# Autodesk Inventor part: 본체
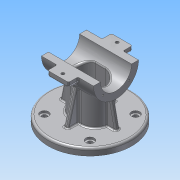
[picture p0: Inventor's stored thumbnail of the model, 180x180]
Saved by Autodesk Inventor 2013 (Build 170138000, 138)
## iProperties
Created: 2015-12
Part Number: 본체
Material: 알루미늄 6061
Document SubType Name: Modeling
Designer: mduedu
Density: 2.71 g/cm^3
Mass: 580.908 g
Surface Area: 555.601 cm^2
Volume: 214.357 cm^3
Author: mduedu
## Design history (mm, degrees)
sketch "스케치1"
  geometry: L1 (45, 40)-(-45, 40); L2 (-45, 40)-(-45, -40); L3 (-45, -40)-(45, -40); L4 (45, -40)-(45, 40); L5 (45, 40)-(-45, -40); L6 (-45, 40)-(45, -40); 2 further points
  constraints: 12 end point, 2 midpoint, 2 parallel, 1 coincident, 1 horizontal, 1 perpendicular, 3 other
  dimensions: "d0" = 90 distance of L2.end L3.end; "d2" = 80 distance of L1.end L2.end
extrude "돌출1" new body sketch "스케치1" distance "d3" = 10; taper "d4" = 0 deg
sketch "스케치2"
  geometry: C1 r 32.5 at (80, 0); 1 further point
  constraints: 1 centre point
  dimensions: "d5" = 65 diameter of C1; "d116" = 80 distance of point (0, 0) C1.centre
extrude "돌출2" join sketch "스케치2" stored distance "d7" = 75; taper "d8" = 0 deg
sketch "스케치3"
  geometry: L1 (-27.5, -20)-(27.5, -20); L2 (27.5, -20)-(27.5, 20); L3 (27.5, 20)-(-27.5, 20); L4 (-27.5, 20)-(-27.5, -20); L5 (-27.5, -20)-(27.5, 20); L6 (27.5, -20)-(-27.5, 20); 1 further point
  constraints: 12 end point, 2 midpoint, 2 parallel, 1 horizontal, 1 perpendicular
  dimensions: "d9" = 55 distance of L2.end L3.end; "d11" = 40 distance of L1.end L2.end
extrude "돌출3" new body sketch "스케치3" stored distance "d12" = 75; taper "d13" = 0 deg
fillet "모깎기1"
fillet "모깎기2"
feature "결합1"
  node "솔리드2"
sketch "스케치4"
  geometry: L1 (-37.5, 47.5)-(37.5, 47.5) reference; L2 (32.5, 47.5)-(40.208, 10); L3 (37.5, 47.5)-(37.5, 112.5) reference; L4 (60.208, 0)-(60.208, 10) reference; L5 (60.208, 10)-(-60.208, 10) reference; 1 further point
  constraints: 2 end point, 2 point on line
  dimensions: "d15" = 5 distance from line of L2.start L3; "d117" = 20 distance from line of L2.end L4
sketch "스케치5"
  geometry: L1 (10, 35.208)-(56.729, 22.687); L2 (0, 60.208)-(10, 60.208) reference; L3 (10, -60.208)-(10, 60.208) reference; 2 further points
  constraints: 2 end point, 1 point on line, 2 other
  dimensions: "d118" = 25 distance from line of L1.start L2; "d119" = 75 deg angle of L1 L3
feature "리브1" dims "d19" = 1, "d20" = 6, "d21" = 0, "d22" = 0, "d23" = 1, "d24" = 1
feature "리브2" dims "d25" = 1, "d26" = 6, "d27" = 0, "d28" = 0, "d29" = 1, "d30" = 1
fillet "모깎기4" dims "d31" = 2
fillet "모깎기5" dims "d32" = 2
fillet "모깎기6" dims "d33" = 2
sketch "스케치6"
  geometry: L1 (0, 0)-(-32.88, 32.88); L2 (0, 0)-(-46.5, 0); A1 r 46.5 centre (0, 0) between (-32.88, 32.88) and (-46.5, 0); 5 further points
  constraints: 4 end point, 2 coincident, 2 point on circle, 1 centre point, 1 horizontal, 5 other
  dimensions: "d120" = 93 diameter of A1; "d122" = 45 deg angle of L1 L2; "d126" = 360 deg dimension on point (0, 0) point (-32.88, 32.88) (derived)
hole "구멍1" sketch "스케치6" at (-32.88, 32.88), (-32.88, -32.88), (32.88, -32.88), (32.88, 32.88) diameter "d34" = 7; stored, may be unused: countersink angle "d38" = 90 deg, drill point angle "d40" = 118 deg; dims "d35" = 6, "d36" = 12, "d37" = 3, "d39" = 8
fillet "모깎기13" dims "d131" = 3
hole "구멍2" diameter "d44" = 45; stored, may be unused: countersink angle "d48" = 90 deg, drill point angle "d50" = 118 deg; dims "d42" = 10, "d43" = 10, "d45" = 6, "d46" = 4, "d47" = 2, "d49" = 8
sketch "스케치7" dims "d52" = 26.5
  geometry: L1 (0, 0)-(32.5, 0); L2 (0, 0)-(22.981, 22.981); A1 r 32.5 centre (0, 0) between (32.5, 0) and (22.981, 22.981) reference; 3 further points
  constraints: 4 end point, 2 point on circle, 1 coincident, 1 horizontal, 1 point on line, 3 other
  dimensions: "d51" = 45 deg angle of L2 L1
hole "구멍3" sketch "스케치7" at (18.738, 18.738) diameter "d54" = 2.459; stored, may be unused: countersink angle "d58" = 90 deg, drill point angle "d60" = 118 deg; dims "d55" = 8, "d56" = 4, "d57" = 2, "d59" = 10
sketch "스케치8"
  geometry: L1 (72.5, 31.623)-(72.5, 46); L2 (72.5, 46)-(87.5, 46); L3 (87.5, 46)-(87.5, 31.623); A1 r 32.5 centre (80, 0) between (87.5, 31.623) and (72.5, 31.623) reference; 2 further points
  constraints: 6 end point, 2 point on circle, 1 horizontal, 1 midpoint, 1 parallel, 1 vertical, 1 vertical alignment
  dimensions: "d64" = 15 distance of L1.end L2.end; "d66" = 46 distance from line of L2 A1.centre
extrude "돌출4" join sketch "스케치8" stored distance "d67" = 30; taper "d68" = 0 deg
fillet "모깎기8" dims "d69" = 3
fillet "모깎기9" dims "d70" = 2
node "작업 평면2"
sketch "스케치16"
  geometry: L1 (33.166, 72.5)-(44, 72.5) reference; L2 (42.5, 72.5)-(28.53, 64.434); L3 (46, 75.5)-(46, 84.5) reference; 2 further points
  constraints: 2 end point, 1 point on line, 2 other
  dimensions: "d138" = 30 deg angle of L2 L1; "d139" = 3.5 distance from line of L2.start L3
feature "리브3" sketch "스케치16" dims "d140" = 1, "d141" = 3, "d142" = 0, "d143" = 0, "d144" = 1, "d145" = 1
fillet "모깎기14" dims "d146" = 1
fillet "모깎기15" dims "d147" = 1
sketch "스케치9"
  geometry: L1 (-76, 82.5)-(76, 82.5); L2 (76, 82.5)-(76, 0); L3 (76, 0)-(-76, 0); L4 (-76, 0)-(-76, 82.5); L5 (-46, 4.5)-(-46, -4.5) reference; C1 r 32.5 at (0, 0) reference; 2 further points
  constraints: 8 end point, 2 parallel, 1 coincident, 1 horizontal, 1 midpoint, 1 perpendicular
  dimensions: "d71" = 50 distance edge to line of C1 L1; "d72" = 30 distance between parallel lines of L4 L5
extrude "돌출5" cut sketch "스케치9" stored distance "d73" = 0; taper "d74" = 0 deg
node "작업 평면1"
sketch "스케치10"
  geometry: L1 (-7.5, 15)-(7.5, 15); L2 (-7.5, -15)-(7.5, -15); A1 r 20 centre (-7.5, 0) between (-7.5, 20) and (-26.977, 4.545) reference; A2 r 20 centre (7.5, 0) between (26.977, 4.545) and (7.5, 20) reference; A3 r 15 centre (-7.5, 0) between (-7.5, 15) and (-7.5, -15); A4 r 15 centre (7.5, 0) between (7.5, -15) and (7.5, 15); 1 further point
  constraints: 7 point on circle, 4 end point, 4 tangent, 3 point on line, 2 centre point, 2 coincident, 1 horizontal
  dimensions: "d77" = 5 radial gap between concentric circles of A3 A1
extrude "돌출6" cut sketch "스케치10" stored distance "d78" = 50; taper "d79" = 0 deg
fillet "모깎기10" dims "d80" = 3
sketch "스케치11"
  geometry: 2 further points
  constraints: 1 coincident
hole "구멍4" sketch "스케치11" at (0, 0) diameter "d81" = 12; stored, may be unused: countersink angle "d85" = 90 deg, drill point angle "d87" = 118 deg; dims "d82" = 8, "d83" = 40, "d84" = 10, "d86" = 10
sketch "스케치12"
  geometry: C1 r 10 at (0, 0); 1 further point
  constraints: 1 centre point, 1 coincident
  dimensions: "d88" = 20 diameter of C1
extrude "돌출7" cut sketch "스케치12" distance "d89" = 5; taper "d90" = 0 deg
chamfer "모따기1" distance "d91" = 1; stored, may be unused: second distance "d92" = 2, angle "d93" = 45 deg
fillet "모깎기11" dims "d94" = 0.5
sketch "스케치13"
  geometry: L1 (-3, 10.834)-(-3, 1.039) reference; L2 (27, 1.039)-(27, 10.834) reference; L3 (-3, 5.936)-(27, 5.936); L4 (24, 12.834)-(0, 12.834) reference; L5 (12, 12.834)-(12, -33.166); 1 further point
  constraints: 4 end point, 4 midpoint, 1 perpendicular, 1 point on line
hole "구멍5" sketch "스케치13" at (12, 5.936) diameter "d101" = 4.5; stored, may be unused: countersink angle "d105" = 90 deg, drill point angle "d107" = 0 deg; dims "d102" = 6, "d103" = 4, "d104" = 2, "d106" = 8
fillet "모깎기12" dims "d115" = 0.3
node "솔리드1"
mirror "대칭1"
mirror "대칭2"
pattern_circular "원형 패턴1" dims angle "d62" = 360 deg
mirror "대칭3"
mirror "대칭7"
mirror "대칭4"
mirror "대칭6"
other parameters: "d137" = -5
